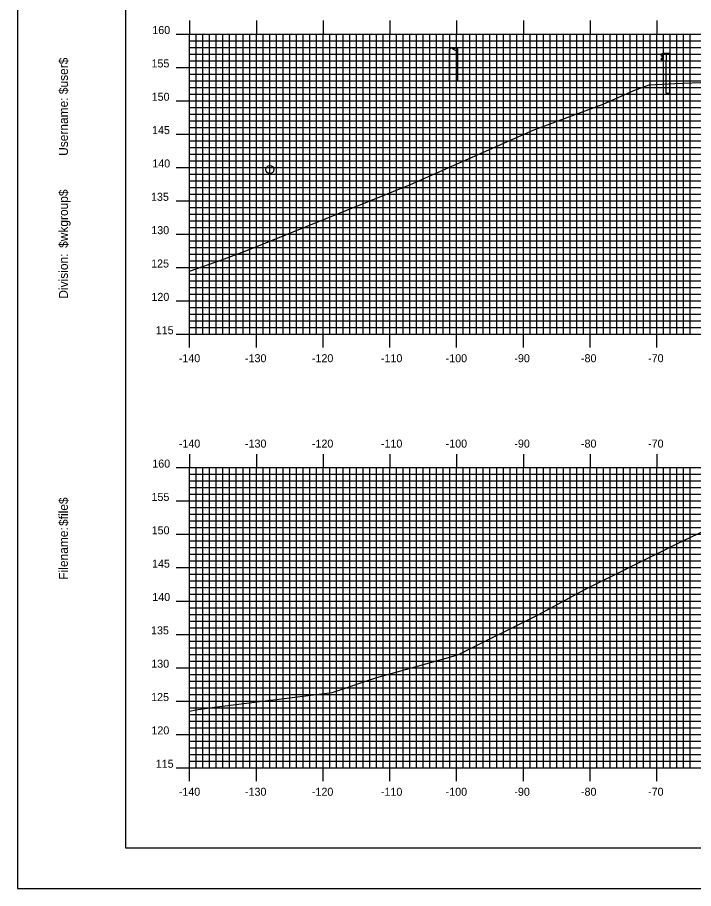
# Model space of a CAD drawing. Extents: x 861045 to 861388, y 364765 to 364985.
# Drawn here: x 861045.1 to 861146.4, y 364765.2 to 364895.8 of the extents above; entities that cross this region are included whole.
import ezdxf

# ---------------------------------------------------------------- set-up
doc = ezdxf.new("R2010")
doc.units = 0
for name, color, linetype in [('BORDER', 7, 'Continuous'), ('H_V ANNOTATION', 7, 'Continuous'), ('M_Guardrail', 7, 'Continuous'), ('M_Utilities_Pole_StreetLight', 7, 'Continuous'), ('MAJOR', 7, 'Continuous'), ('MINOR', 7, 'Continuous'), ('PLOT BOUNDARY', 7, 'Continuous'), ('S_Drainage_Invert', 7, 'Continuous'), ('S_Roadway_Centerline', 7, 'Continuous')]:
    doc.layers.add(name, color=color, linetype=linetype)

msp = doc.modelspace()

# ---------------------------------------------------------------- linework, layer by layer
at = {"layer": 'BORDER'}
msp.add_lwpolyline([(861061.33, 364771.3), (861381.33, 364771.3), (861381.33, 364981.3), (861061.33, 364981.3)], close=True, dxfattribs=at)
at = {"layer": 'M_Guardrail'}
for p, q in [((861141.72, 364890.32), (861141.58, 364890.22)), ((861141.82, 364890.35), (861141.74, 364890.33)), ((861141.82, 364890.42), (861142.31, 364890.42)), ((861141.82, 364889.25), (861141.82, 364890.42)), ((861142.31, 364890.42), (861142.8, 364890.42)), ((861142.31, 364890.42), (861142.31, 364889.25)), ((861142.8, 364890.42), (861142.8, 364884.42)), ((861141.58, 364890.08), (861141.77, 364889.94)), ((861141.77, 364889.73), (861141.58, 364889.59)), ((861141.58, 364889.45), (861141.72, 364889.35)), ((861141.74, 364889.34), (861141.82, 364889.32)), ((861141.81, 364889.88), (861141.81, 364889.79)), ((861142.31, 364889.25), (861141.82, 364889.25)), ((861142.31, 364884.42), (861142.31, 364889.25)), ((861142.31, 364884.42), (861142.8, 364884.42))]:
    msp.add_line(p, q, dxfattribs=at)
for centre, major_axis, start_param, end_param in [((861141.63, 364890.15), (-0.0877, 0), 5.323254, 7.243116), ((861141.74, 364890.29), (-0.0417, 0), 4.886922, 5.323254), ((861141.63, 364889.52), (-0.0877, 0), 5.323254, 7.243116), ((861141.74, 364889.38), (-0.0417, 0), 0.959931, 1.396263), ((861141.73, 364889.88), (0.0789, 0), 0, 0.959931), ((861141.73, 364889.79), (0.0789, 0), 5.323254, 6.283185)]:
    msp.add_ellipse(centre, major_axis=major_axis, ratio=0.995501, start_param=start_param, end_param=end_param, dxfattribs=at)
at = {"layer": 'M_Utilities_Pole_StreetLight'}
for p, q in [((861109.85, 364886.41), (861109.84, 364891.03)), ((861109.85, 364891.03), (861110, 364891.14)), ((861110.31, 364891.14), (861110.47, 364891.03)), ((861110.63, 364891.14), (861110.47, 364891.03)), ((861110.47, 364891.03), (861110.63, 364890.92)), ((861111.1, 364891.03), (861110.94, 364891.14)), ((861110.94, 364890.92), (861111.1, 364891.03)), ((861111.1, 364886.41), (861111.09, 364891.03))]:
    msp.add_line(p, q, dxfattribs=at)
for centre, start, end in [((861110.16, 364890.92), 90, 125.2644), ((861110.16, 364890.92), 54.7356, 90), ((861110.78, 364890.92), 90, 125.2644), ((861110.78, 364891.14), 234.7356, 270), ((861110.78, 364890.92), 54.7356, 90), ((861110.78, 364891.14), 270, 305.2644)]:
    msp.add_arc(centre, 0.271, start, end, dxfattribs=at)
at = {"layer": 'MAJOR'}
for p, q in [((861070.93, 364895.31), (861070.93, 364893.3)), ((861080.93, 364895.31), (861080.93, 364893.3)), ((861090.93, 364895.31), (861090.93, 364893.3)), ((861100.93, 364895.31), (861100.93, 364893.3)), ((861110.93, 364895.31), (861110.93, 364893.3)), ((861120.93, 364895.31), (861120.93, 364893.3)), ((861130.93, 364895.31), (861130.93, 364893.3)), ((861140.93, 364895.31), (861140.93, 364893.3)), ((861068.92, 364893.3), (861070.93, 364893.3)), ((861070.93, 364893.3), (861350.93, 364893.3)), ((861070.93, 364848.3), (861070.93, 364893.3)), ((861070.93, 364848.3), (861070.93, 364893.3)), ((861070.93, 364893.3), (861350.93, 364893.3)), ((861080.93, 364848.3), (861080.93, 364893.3)), ((861090.93, 364848.3), (861090.93, 364893.3)), ((861100.93, 364848.3), (861100.93, 364893.3)), ((861110.93, 364848.3), (861110.93, 364893.3)), ((861120.93, 364848.3), (861120.93, 364893.3)), ((861130.93, 364848.3), (861130.93, 364893.3)), ((861140.93, 364848.3), (861140.93, 364893.3)), ((861068.92, 364888.3), (861070.93, 364888.3)), ((861070.93, 364888.3), (861350.93, 364888.3)), ((861068.92, 364883.3), (861070.93, 364883.3)), ((861070.93, 364883.3), (861350.93, 364883.3)), ((861068.92, 364878.3), (861070.93, 364878.3)), ((861070.93, 364878.3), (861350.93, 364878.3)), ((861068.92, 364873.3), (861070.93, 364873.3)), ((861070.93, 364873.3), (861350.93, 364873.3)), ((861068.92, 364868.3), (861070.93, 364868.3)), ((861070.93, 364868.3), (861350.93, 364868.3)), ((861068.92, 364863.3), (861070.93, 364863.3)), ((861070.93, 364863.3), (861350.93, 364863.3)), ((861068.92, 364858.3), (861070.93, 364858.3)), ((861070.93, 364858.3), (861350.93, 364858.3)), ((861068.92, 364853.3), (861070.93, 364853.3)), ((861070.93, 364853.3), (861350.93, 364853.3)), ((861068.92, 364848.3), (861070.93, 364848.3)), ((861070.93, 364848.3), (861350.93, 364848.3)), ((861070.93, 364848.3), (861350.93, 364848.3)), ((861070.93, 364846.3), (861070.93, 364848.3)), ((861080.93, 364846.3), (861080.93, 364848.3)), ((861090.93, 364846.3), (861090.93, 364848.3)), ((861100.93, 364846.3), (861100.93, 364848.3)), ((861110.93, 364846.3), (861110.93, 364848.3)), ((861120.93, 364846.3), (861120.93, 364848.3)), ((861130.93, 364846.3), (861130.93, 364848.3)), ((861140.93, 364846.3), (861140.93, 364848.3)), ((861070.93, 364830.31), (861070.93, 364828.3)), ((861080.93, 364830.31), (861080.93, 364828.3)), ((861090.93, 364830.31), (861090.93, 364828.3)), ((861100.93, 364830.31), (861100.93, 364828.3)), ((861110.93, 364830.31), (861110.93, 364828.3)), ((861120.93, 364830.31), (861120.93, 364828.3)), ((861130.93, 364830.31), (861130.93, 364828.3)), ((861140.93, 364830.31), (861140.93, 364828.3)), ((861068.92, 364828.3), (861070.93, 364828.3)), ((861070.93, 364828.3), (861350.93, 364828.3)), ((861070.93, 364783.3), (861070.93, 364828.3)), ((861070.93, 364783.3), (861070.93, 364828.3)), ((861070.93, 364828.3), (861350.93, 364828.3)), ((861080.93, 364783.3), (861080.93, 364828.3)), ((861090.93, 364783.3), (861090.93, 364828.3)), ((861100.93, 364783.3), (861100.93, 364828.3)), ((861110.93, 364783.3), (861110.93, 364828.3)), ((861120.93, 364783.3), (861120.93, 364828.3)), ((861130.93, 364783.3), (861130.93, 364828.3)), ((861140.93, 364783.3), (861140.93, 364828.3)), ((861068.92, 364823.3), (861070.93, 364823.3)), ((861070.93, 364823.3), (861350.93, 364823.3)), ((861068.92, 364818.3), (861070.93, 364818.3)), ((861070.93, 364818.3), (861350.93, 364818.3)), ((861068.92, 364813.3), (861070.93, 364813.3)), ((861070.93, 364813.3), (861350.93, 364813.3)), ((861068.92, 364808.3), (861070.93, 364808.3)), ((861070.93, 364808.3), (861350.93, 364808.3)), ((861068.92, 364803.3), (861070.93, 364803.3)), ((861070.93, 364803.3), (861350.93, 364803.3)), ((861068.92, 364798.3), (861070.93, 364798.3)), ((861070.93, 364798.3), (861350.93, 364798.3)), ((861068.92, 364793.3), (861070.93, 364793.3)), ((861070.93, 364793.3), (861350.93, 364793.3)), ((861068.92, 364788.3), (861070.93, 364788.3)), ((861070.93, 364788.3), (861350.93, 364788.3)), ((861068.92, 364783.3), (861070.93, 364783.3)), ((861070.93, 364783.3), (861350.93, 364783.3)), ((861070.93, 364783.3), (861350.93, 364783.3)), ((861070.93, 364781.3), (861070.93, 364783.3)), ((861080.93, 364781.3), (861080.93, 364783.3)), ((861090.93, 364781.3), (861090.93, 364783.3)), ((861100.93, 364781.3), (861100.93, 364783.3)), ((861110.93, 364781.3), (861110.93, 364783.3)), ((861120.93, 364781.3), (861120.93, 364783.3)), ((861130.93, 364781.3), (861130.93, 364783.3)), ((861140.93, 364781.3), (861140.93, 364783.3))]:
    msp.add_line(p, q, dxfattribs=at)
at = {"layer": 'MINOR'}
for p, q in [((861071.93, 364848.3), (861071.93, 364893.3)), ((861072.93, 364848.3), (861072.93, 364893.3)), ((861073.93, 364848.3), (861073.93, 364893.3)), ((861074.93, 364848.3), (861074.93, 364893.3)), ((861075.93, 364848.3), (861075.93, 364893.3)), ((861076.93, 364848.3), (861076.93, 364893.3)), ((861077.93, 364848.3), (861077.93, 364893.3)), ((861078.93, 364848.3), (861078.93, 364893.3)), ((861079.93, 364848.3), (861079.93, 364893.3)), ((861081.93, 364848.3), (861081.93, 364893.3)), ((861082.93, 364848.3), (861082.93, 364893.3)), ((861083.93, 364848.3), (861083.93, 364893.3)), ((861084.93, 364848.3), (861084.93, 364893.3)), ((861085.93, 364848.3), (861085.93, 364893.3)), ((861086.93, 364848.3), (861086.93, 364893.3)), ((861087.93, 364848.3), (861087.93, 364893.3)), ((861088.93, 364848.3), (861088.93, 364893.3)), ((861089.93, 364848.3), (861089.93, 364893.3)), ((861091.93, 364848.3), (861091.93, 364893.3)), ((861092.93, 364848.3), (861092.93, 364893.3)), ((861093.93, 364848.3), (861093.93, 364893.3)), ((861094.93, 364848.3), (861094.93, 364893.3)), ((861095.93, 364848.3), (861095.93, 364893.3)), ((861096.93, 364848.3), (861096.93, 364893.3)), ((861097.93, 364848.3), (861097.93, 364893.3)), ((861098.93, 364848.3), (861098.93, 364893.3)), ((861099.93, 364848.3), (861099.93, 364893.3)), ((861101.93, 364848.3), (861101.93, 364893.3)), ((861102.93, 364848.3), (861102.93, 364893.3)), ((861103.93, 364848.3), (861103.93, 364893.3)), ((861104.93, 364848.3), (861104.93, 364893.3)), ((861105.93, 364848.3), (861105.93, 364893.3)), ((861106.93, 364848.3), (861106.93, 364893.3)), ((861107.93, 364848.3), (861107.93, 364893.3)), ((861108.93, 364848.3), (861108.93, 364893.3)), ((861109.93, 364848.3), (861109.93, 364893.3)), ((861111.93, 364848.3), (861111.93, 364893.3)), ((861112.93, 364848.3), (861112.93, 364893.3)), ((861113.93, 364848.3), (861113.93, 364893.3)), ((861114.93, 364848.3), (861114.93, 364893.3)), ((861115.93, 364848.3), (861115.93, 364893.3)), ((861116.93, 364848.3), (861116.93, 364893.3)), ((861117.93, 364848.3), (861117.93, 364893.3)), ((861118.93, 364848.3), (861118.93, 364893.3)), ((861119.93, 364848.3), (861119.93, 364893.3)), ((861121.93, 364848.3), (861121.93, 364893.3)), ((861122.93, 364848.3), (861122.93, 364893.3)), ((861123.93, 364848.3), (861123.93, 364893.3)), ((861124.93, 364848.3), (861124.93, 364893.3)), ((861125.93, 364848.3), (861125.93, 364893.3)), ((861126.93, 364848.3), (861126.93, 364893.3)), ((861127.93, 364848.3), (861127.93, 364893.3)), ((861128.93, 364848.3), (861128.93, 364893.3)), ((861129.93, 364848.3), (861129.93, 364893.3)), ((861131.93, 364848.3), (861131.93, 364893.3)), ((861132.93, 364848.3), (861132.93, 364893.3)), ((861133.93, 364848.3), (861133.93, 364893.3)), ((861134.93, 364848.3), (861134.93, 364893.3)), ((861135.93, 364848.3), (861135.93, 364893.3)), ((861136.93, 364848.3), (861136.93, 364893.3)), ((861137.93, 364848.3), (861137.93, 364893.3)), ((861138.93, 364848.3), (861138.93, 364893.3)), ((861139.93, 364848.3), (861139.93, 364893.3)), ((861141.93, 364848.3), (861141.93, 364893.3)), ((861142.93, 364848.3), (861142.93, 364893.3)), ((861143.93, 364848.3), (861143.93, 364893.3)), ((861144.93, 364848.3), (861144.93, 364893.3)), ((861145.93, 364848.3), (861145.93, 364893.3)), ((861070.93, 364892.3), (861350.93, 364892.3)), ((861070.93, 364892.3), (861072.93, 364892.3)), ((861070.93, 364891.3), (861350.93, 364891.3)), ((861070.93, 364891.3), (861072.93, 364891.3)), ((861070.93, 364890.3), (861350.93, 364890.3)), ((861070.93, 364890.3), (861072.93, 364890.3)), ((861070.93, 364889.3), (861350.93, 364889.3)), ((861070.93, 364889.3), (861072.93, 364889.3)), ((861070.93, 364887.3), (861350.93, 364887.3)), ((861070.93, 364887.3), (861072.93, 364887.3)), ((861070.93, 364886.3), (861350.93, 364886.3)), ((861070.93, 364886.3), (861072.93, 364886.3)), ((861070.93, 364885.3), (861350.93, 364885.3)), ((861070.93, 364885.3), (861072.93, 364885.3)), ((861070.93, 364884.3), (861350.93, 364884.3)), ((861070.93, 364884.3), (861072.93, 364884.3)), ((861070.93, 364882.3), (861350.93, 364882.3)), ((861070.93, 364882.3), (861072.93, 364882.3)), ((861070.93, 364881.3), (861350.93, 364881.3)), ((861070.93, 364881.3), (861072.93, 364881.3)), ((861070.93, 364880.3), (861350.93, 364880.3)), ((861070.93, 364880.3), (861072.93, 364880.3)), ((861070.93, 364879.3), (861350.93, 364879.3)), ((861070.93, 364879.3), (861072.93, 364879.3)), ((861070.93, 364877.3), (861350.93, 364877.3)), ((861070.93, 364877.3), (861072.93, 364877.3)), ((861070.93, 364876.3), (861350.93, 364876.3)), ((861070.93, 364876.3), (861072.93, 364876.3)), ((861070.93, 364875.3), (861350.93, 364875.3)), ((861070.93, 364875.3), (861072.93, 364875.3)), ((861070.93, 364874.3), (861350.93, 364874.3)), ((861070.93, 364874.3), (861072.93, 364874.3)), ((861070.93, 364872.3), (861350.93, 364872.3)), ((861070.93, 364872.3), (861072.93, 364872.3)), ((861070.93, 364871.3), (861350.93, 364871.3)), ((861070.93, 364871.3), (861072.93, 364871.3)), ((861070.93, 364870.3), (861350.93, 364870.3)), ((861070.93, 364870.3), (861072.93, 364870.3)), ((861070.93, 364869.3), (861350.93, 364869.3)), ((861070.93, 364869.3), (861072.93, 364869.3)), ((861070.93, 364867.3), (861350.93, 364867.3)), ((861070.93, 364867.3), (861072.93, 364867.3)), ((861070.93, 364866.3), (861350.93, 364866.3)), ((861070.93, 364866.3), (861072.93, 364866.3)), ((861070.93, 364865.3), (861350.93, 364865.3)), ((861070.93, 364865.3), (861072.93, 364865.3)), ((861070.93, 364864.3), (861350.93, 364864.3)), ((861070.93, 364864.3), (861072.93, 364864.3)), ((861070.93, 364862.3), (861350.93, 364862.3)), ((861070.93, 364862.3), (861072.93, 364862.3)), ((861070.93, 364861.3), (861350.93, 364861.3)), ((861070.93, 364861.3), (861072.93, 364861.3)), ((861070.93, 364860.3), (861350.93, 364860.3)), ((861070.93, 364860.3), (861072.93, 364860.3)), ((861070.93, 364859.3), (861350.93, 364859.3)), ((861070.93, 364859.3), (861072.93, 364859.3)), ((861070.93, 364857.3), (861350.93, 364857.3)), ((861070.93, 364857.3), (861072.93, 364857.3)), ((861070.93, 364856.3), (861350.93, 364856.3)), ((861070.93, 364856.3), (861072.93, 364856.3)), ((861070.93, 364855.3), (861350.93, 364855.3)), ((861070.93, 364855.3), (861072.93, 364855.3)), ((861070.93, 364854.3), (861350.93, 364854.3)), ((861070.93, 364854.3), (861072.93, 364854.3)), ((861070.93, 364852.3), (861350.93, 364852.3)), ((861070.93, 364852.3), (861072.93, 364852.3)), ((861070.93, 364851.3), (861350.93, 364851.3)), ((861070.93, 364851.3), (861072.93, 364851.3)), ((861070.93, 364850.3), (861350.93, 364850.3)), ((861070.93, 364850.3), (861072.93, 364850.3)), ((861070.93, 364849.3), (861350.93, 364849.3)), ((861070.93, 364849.3), (861072.93, 364849.3)), ((861071.93, 364783.3), (861071.93, 364828.3)), ((861072.93, 364783.3), (861072.93, 364828.3)), ((861073.93, 364783.3), (861073.93, 364828.3)), ((861074.93, 364783.3), (861074.93, 364828.3)), ((861075.93, 364783.3), (861075.93, 364828.3)), ((861076.93, 364783.3), (861076.93, 364828.3)), ((861077.93, 364783.3), (861077.93, 364828.3)), ((861078.93, 364783.3), (861078.93, 364828.3)), ((861079.93, 364783.3), (861079.93, 364828.3)), ((861081.93, 364783.3), (861081.93, 364828.3)), ((861082.93, 364783.3), (861082.93, 364828.3)), ((861083.93, 364783.3), (861083.93, 364828.3)), ((861084.93, 364783.3), (861084.93, 364828.3)), ((861085.93, 364783.3), (861085.93, 364828.3)), ((861086.93, 364783.3), (861086.93, 364828.3)), ((861087.93, 364783.3), (861087.93, 364828.3)), ((861088.93, 364783.3), (861088.93, 364828.3)), ((861089.93, 364783.3), (861089.93, 364828.3)), ((861091.93, 364783.3), (861091.93, 364828.3)), ((861092.93, 364783.3), (861092.93, 364828.3)), ((861093.93, 364783.3), (861093.93, 364828.3)), ((861094.93, 364783.3), (861094.93, 364828.3)), ((861095.93, 364783.3), (861095.93, 364828.3)), ((861096.93, 364783.3), (861096.93, 364828.3)), ((861097.93, 364783.3), (861097.93, 364828.3)), ((861098.93, 364783.3), (861098.93, 364828.3)), ((861099.93, 364783.3), (861099.93, 364828.3)), ((861101.93, 364783.3), (861101.93, 364828.3)), ((861102.93, 364783.3), (861102.93, 364828.3)), ((861103.93, 364783.3), (861103.93, 364828.3)), ((861104.93, 364783.3), (861104.93, 364828.3)), ((861105.93, 364783.3), (861105.93, 364828.3)), ((861106.93, 364783.3), (861106.93, 364828.3)), ((861107.93, 364783.3), (861107.93, 364828.3)), ((861108.93, 364783.3), (861108.93, 364828.3)), ((861109.93, 364783.3), (861109.93, 364828.3)), ((861111.93, 364783.3), (861111.93, 364828.3)), ((861112.93, 364783.3), (861112.93, 364828.3)), ((861113.93, 364783.3), (861113.93, 364828.3)), ((861114.93, 364783.3), (861114.93, 364828.3)), ((861115.93, 364783.3), (861115.93, 364828.3)), ((861116.93, 364783.3), (861116.93, 364828.3)), ((861117.93, 364783.3), (861117.93, 364828.3)), ((861118.93, 364783.3), (861118.93, 364828.3)), ((861119.93, 364783.3), (861119.93, 364828.3)), ((861121.93, 364783.3), (861121.93, 364828.3)), ((861122.93, 364783.3), (861122.93, 364828.3)), ((861123.93, 364783.3), (861123.93, 364828.3)), ((861124.93, 364783.3), (861124.93, 364828.3)), ((861125.93, 364783.3), (861125.93, 364828.3)), ((861126.93, 364783.3), (861126.93, 364828.3)), ((861127.93, 364783.3), (861127.93, 364828.3)), ((861128.93, 364783.3), (861128.93, 364828.3)), ((861129.93, 364783.3), (861129.93, 364828.3)), ((861131.93, 364783.3), (861131.93, 364828.3)), ((861132.93, 364783.3), (861132.93, 364828.3)), ((861133.93, 364783.3), (861133.93, 364828.3)), ((861134.93, 364783.3), (861134.93, 364828.3)), ((861135.93, 364783.3), (861135.93, 364828.3)), ((861136.93, 364783.3), (861136.93, 364828.3)), ((861137.93, 364783.3), (861137.93, 364828.3)), ((861138.93, 364783.3), (861138.93, 364828.3)), ((861139.93, 364783.3), (861139.93, 364828.3)), ((861141.93, 364783.3), (861141.93, 364828.3)), ((861142.93, 364783.3), (861142.93, 364828.3)), ((861143.93, 364783.3), (861143.93, 364828.3)), ((861144.93, 364783.3), (861144.93, 364828.3)), ((861145.93, 364783.3), (861145.93, 364828.3)), ((861070.93, 364827.3), (861350.93, 364827.3)), ((861070.93, 364827.3), (861072.93, 364827.3)), ((861070.93, 364826.3), (861350.93, 364826.3)), ((861070.93, 364826.3), (861072.93, 364826.3)), ((861070.93, 364825.3), (861350.93, 364825.3)), ((861070.93, 364825.3), (861072.93, 364825.3)), ((861070.93, 364824.3), (861350.93, 364824.3)), ((861070.93, 364824.3), (861072.93, 364824.3)), ((861070.93, 364822.3), (861350.93, 364822.3)), ((861070.93, 364822.3), (861072.93, 364822.3)), ((861070.93, 364821.3), (861350.93, 364821.3)), ((861070.93, 364821.3), (861072.93, 364821.3)), ((861070.93, 364820.3), (861350.93, 364820.3)), ((861070.93, 364820.3), (861072.93, 364820.3)), ((861070.93, 364819.3), (861350.93, 364819.3)), ((861070.93, 364819.3), (861072.93, 364819.3)), ((861070.93, 364817.3), (861350.93, 364817.3)), ((861070.93, 364817.3), (861072.93, 364817.3)), ((861070.93, 364816.3), (861350.93, 364816.3)), ((861070.93, 364816.3), (861072.93, 364816.3)), ((861070.93, 364815.3), (861350.93, 364815.3)), ((861070.93, 364815.3), (861072.93, 364815.3)), ((861070.93, 364814.3), (861350.93, 364814.3)), ((861070.93, 364814.3), (861072.93, 364814.3)), ((861070.93, 364812.3), (861350.93, 364812.3)), ((861070.93, 364812.3), (861072.93, 364812.3)), ((861070.93, 364811.3), (861350.93, 364811.3)), ((861070.93, 364811.3), (861072.93, 364811.3)), ((861070.93, 364810.3), (861350.93, 364810.3)), ((861070.93, 364810.3), (861072.93, 364810.3)), ((861070.93, 364809.3), (861350.93, 364809.3)), ((861070.93, 364809.3), (861072.93, 364809.3)), ((861070.93, 364807.3), (861350.93, 364807.3)), ((861070.93, 364807.3), (861072.93, 364807.3)), ((861070.93, 364806.3), (861350.93, 364806.3)), ((861070.93, 364806.3), (861072.93, 364806.3)), ((861070.93, 364805.3), (861350.93, 364805.3)), ((861070.93, 364805.3), (861072.93, 364805.3)), ((861070.93, 364804.3), (861350.93, 364804.3)), ((861070.93, 364804.3), (861072.93, 364804.3)), ((861070.93, 364802.3), (861350.93, 364802.3)), ((861070.93, 364802.3), (861072.93, 364802.3)), ((861070.93, 364801.3), (861350.93, 364801.3)), ((861070.93, 364801.3), (861072.93, 364801.3)), ((861070.93, 364800.3), (861350.93, 364800.3)), ((861070.93, 364800.3), (861072.93, 364800.3)), ((861070.93, 364799.3), (861350.93, 364799.3)), ((861070.93, 364799.3), (861072.93, 364799.3)), ((861070.93, 364797.3), (861350.93, 364797.3)), ((861070.93, 364797.3), (861072.93, 364797.3)), ((861070.93, 364796.3), (861350.93, 364796.3)), ((861070.93, 364796.3), (861072.93, 364796.3)), ((861070.93, 364795.3), (861350.93, 364795.3)), ((861070.93, 364795.3), (861072.93, 364795.3)), ((861070.93, 364794.3), (861350.93, 364794.3)), ((861070.93, 364794.3), (861072.93, 364794.3)), ((861070.93, 364792.3), (861350.93, 364792.3)), ((861070.93, 364792.3), (861072.93, 364792.3)), ((861070.93, 364791.3), (861350.93, 364791.3)), ((861070.93, 364791.3), (861072.93, 364791.3)), ((861070.93, 364790.3), (861350.93, 364790.3)), ((861070.93, 364790.3), (861072.93, 364790.3)), ((861070.93, 364789.3), (861350.93, 364789.3)), ((861070.93, 364789.3), (861072.93, 364789.3)), ((861070.93, 364787.3), (861350.93, 364787.3)), ((861070.93, 364787.3), (861072.93, 364787.3)), ((861070.93, 364786.3), (861350.93, 364786.3)), ((861070.93, 364786.3), (861072.93, 364786.3)), ((861070.93, 364785.3), (861350.93, 364785.3)), ((861070.93, 364785.3), (861072.93, 364785.3)), ((861070.93, 364784.3), (861350.93, 364784.3)), ((861070.93, 364784.3), (861072.93, 364784.3))]:
    msp.add_line(p, q, dxfattribs=at)
at = {"layer": 'PLOT BOUNDARY'}
msp.add_lwpolyline([(861045.14, 364765.18), (861385.14, 364765.18), (861385.14, 364985.18), (861045.14, 364985.18)], close=True, dxfattribs=at)
at = {"layer": 'S_Drainage_Invert'}
msp.add_circle((861082.95, 364872.99), 0.6, dxfattribs=at)
at = {"layer": 'S_Roadway_Centerline'}
for points in [[(861070.93, 364857.74), (861075.74, 364859.44), (861078.02, 364860.28), (861078.31, 364860.38), (861079.24, 364860.75), (861097.56, 364868.16), (861104, 364870.74), (861122.39, 364878.9), (861128.27, 364881.07), (861132.86, 364882.78), (861137.5, 364884.85), (861139.77, 364885.7), (861143.63, 364885.9), (861148.8, 364886.1)], [(861070.93, 364791.79), (861071.84, 364791.98), (861073.27, 364792.19), (861074.67, 364792.4), (861092.3, 364794.57), (861098.99, 364796.83), (861109.38, 364799.74), (861110.57, 364800.06), (861111.31, 364800.35), (861123.17, 364806.24), (861130.14, 364810.02), (861144.02, 364816.91), (861148.1, 364818.85)]]:
    msp.add_lwpolyline(points, dxfattribs=at)

# ---------------------------------------------------------------- texts
at = {"layer": 'BORDER'}
for s, p in [('$user$', (861052.7, 364884.29)), ('Username:', (861052.7, 364875.04)), ('$wkgroup$', (861052.7, 364861.24)), ('Division:', (861052.7, 364853.63)), ('$file$', (861052.7, 364819.55)), ('Filename:', (861052.7, 364811.5))]:
    msp.add_text(s, height=1.339, rotation=90, dxfattribs=at).set_placement(p)
at = {"layer": 'H_V ANNOTATION'}
for s, p in [('160', (861065.34, 364893.3)), ('155', (861065.22, 364888.3)), ('150', (861065.25, 364883.3)), ('145', (861065.3, 364878.3)), ('140', (861065.34, 364873.3)), ('135', (861065.15, 364868.3)), ('130', (861065.19, 364863.3)), ('125', (861065.17, 364858.3)), ('120', (861065.21, 364853.3)), ('115', (861065.86, 364848.3)), ('-140', (861069.31, 364844.1)), ('-130', (861079.23, 364844.1)), ('-120', (861089.25, 364844.1)), ('-110', (861099.59, 364844.1)), ('-100', (861109.29, 364844.1)), ('-90', (861119.58, 364844.1)), ('-80', (861129.56, 364844.1)), ('-70', (861139.61, 364844.1)), ('-140', (861069.31, 364831.3)), ('-130', (861079.23, 364831.3)), ('-120', (861089.25, 364831.3)), ('-110', (861099.59, 364831.3)), ('-100', (861109.29, 364831.3)), ('-90', (861119.58, 364831.3)), ('-80', (861129.56, 364831.3)), ('-70', (861139.61, 364831.3)), ('160', (861065.34, 364828.3)), ('155', (861065.22, 364823.3)), ('150', (861065.25, 364818.3)), ('145', (861065.3, 364813.3)), ('140', (861065.34, 364808.3)), ('135', (861065.15, 364803.3)), ('130', (861065.19, 364798.3)), ('125', (861065.17, 364793.3)), ('120', (861065.21, 364788.3)), ('115', (861065.86, 364783.3)), ('-140', (861069.31, 364779.1)), ('-130', (861079.23, 364779.1)), ('-120', (861089.25, 364779.1)), ('-110', (861099.59, 364779.1)), ('-100', (861109.29, 364779.1)), ('-90', (861119.58, 364779.1)), ('-80', (861129.56, 364779.1)), ('-70', (861139.61, 364779.1))]:
    msp.add_text(s, height=1.2, dxfattribs=at).set_placement(p)
at = {"layer": 'MAJOR'}
for p in [(861070.92, 364848.3), (861070.92, 364783.3)]:
    msp.add_text('-', height=0.012, dxfattribs=at).set_placement(p)

doc.saveas('drawing.dxf')
